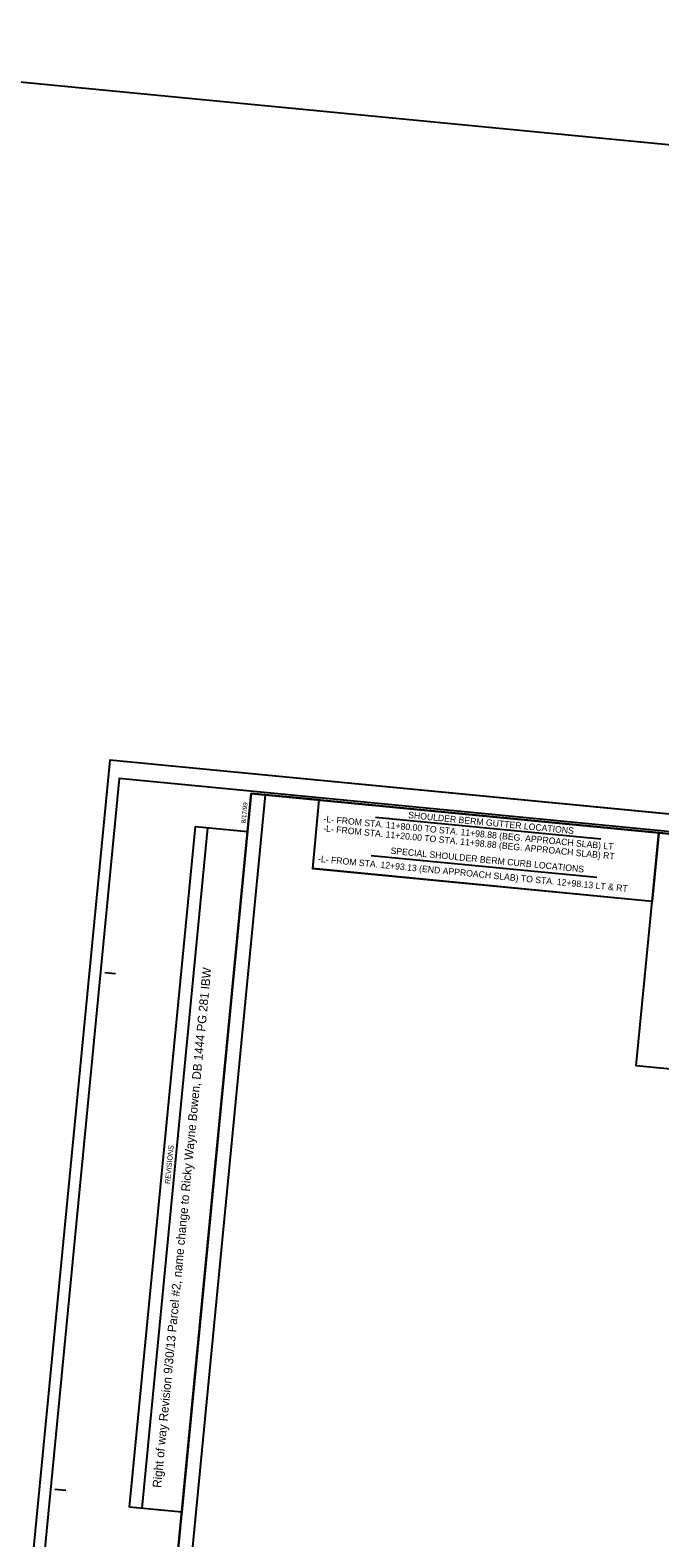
# Model space of a CAD drawing. Extents: x 2060525 to 2062119, y 912110 to 913300.
# Drawn here: x 2060879 to 2061171, y 912603 to 913300 of the extents above; entities that cross this region are included whole.
import ezdxf

# ---------------------------------------------------------------- set-up
doc = ezdxf.new("R2010")
doc.units = 0
for name, color, linetype in [('Prop Conc Shoulder Berm Gutter', 7, 'Continuous'), ('Prop Dimension Text', 7, 'Continuous'), ('Sheet Block Revision CELL', 7, 'Continuous'), ('Sheet Clip Boundary CELL', 7, 'Continuous'), ('Sheet Cutting Line CELL', 7, 'Continuous'), ('Sheet Layout Plan Border', 7, 'Continuous'), ('Sheet Plan CELL', 7, 'Continuous'), ('Sheet Plan Layout CELL', 7, 'Continuous'), ('Sheet Plot Border Inside CELL', 7, 'Continuous'), ('Sheet Plot Border Outside CELL', 7, 'Continuous')]:
    doc.layers.add(name, color=color, linetype=linetype)

msp = doc.modelspace()

# ---------------------------------------------------------------- linework, layer by layer
at = {"layer": 'Prop Conc Shoulder Berm Gutter'}
for p, q in [((2061039.03, 912935.88), (2061143.21, 912925.81)), ((2061037.17, 912918.16), (2061141.35, 912908.09))]:
    msp.add_line(p, q, dxfattribs=at)
at = {"layer": 'Sheet Block Revision CELL'}
msp.add_line((2060931.25, 912616.18), (2060961.67, 912930.97), dxfattribs=at)
msp.add_lwpolyline([(2060925.45, 912616.73), (2060955.88, 912931.52), (2060979.99, 912929.2), (2060949.56, 912614.41)], close=True, dxfattribs=at)
at = {"layer": 'Sheet Clip Boundary CELL'}
msp.add_lwpolyline([(2060947.75, 912528.18), (2061534.24, 912471.49), (2061175.38, 912506.18), (2061182.37, 912578.54), (2061543.72, 912543.62), (2061569, 912805.1), (2061475.51, 912814.14), (2061473.23, 912790.55), (2061159.65, 912820.86), (2061167, 912896.82), (2061010.06, 912911.99), (2061013.14, 912943.82), (2060988.16, 912946.23)], close=True, dxfattribs=at)
at = {"layer": 'Sheet Cutting Line CELL'}
for p, q in [((2060916.27, 912962.22), (2060874.13, 912526.25)), ((2061586.54, 912897.43), (2060916.27, 912962.22))]:
    msp.add_line(p, q, dxfattribs=at)
at = {"layer": 'Sheet Layout Plan Border'}
msp.add_lwpolyline([(2060947.75, 912528.18), (2061530.76, 912471.83), (2061563.03, 912805.68), (2061475.51, 912814.14), (2061483.65, 912898.34), (2060988.16, 912946.23)], close=True, dxfattribs=at)
at = {"layer": 'Sheet Plan CELL'}
for p, q in [((2060981.69, 912946.86), (2060981.69, 912946.86)), ((2060914, 912863.98), (2060918.98, 912863.51)), ((2060890.92, 912625.1), (2060895.9, 912624.61))]:
    msp.add_line(p, q, dxfattribs=at)
for points in [[(2061578.92, 912889.13), (2060981.69, 912946.86), (2060941.28, 912528.81), (2061538.5, 912471.08)], [(2060941.28, 912528.81), (2060981.68, 912946.85), (2061499.26, 912896.83), (2061493.49, 912837.09), (2061573.14, 912829.38), (2061538.5, 912471.08)], [(2061013.14, 912943.82), (2061170.07, 912928.65), (2061167, 912896.82), (2061010.07, 912912.03)], [(2061170.06, 912928.65), (2061483.65, 912898.34), (2061473.22, 912790.47), (2061159.65, 912820.86)]]:
    msp.add_lwpolyline(points, close=True, dxfattribs=at)
at = {"layer": 'Sheet Plan Layout CELL'}
for points in [[(2060625.77, 913299.86), (2060524.78, 912254.76), (2062017.82, 912110.43), (2062098.49, 912945.06), (2061860.35, 912968.08), (2061880.7, 913178.58)], [(2060981.68, 912946.85), (2060941.28, 912528.81), (2061538.5, 912471.08), (2061570.77, 912804.93), (2061475.51, 912814.14), (2061483.65, 912898.34)]]:
    msp.add_lwpolyline(points, close=True, dxfattribs=at)
at = {"layer": 'Sheet Plot Border Inside CELL'}
msp.add_lwpolyline([(2060880.07, 912533.71), (2061543.38, 912469.6), (2061583.98, 912889.64), (2060920.68, 912953.76)], close=True, dxfattribs=at)
at = {"layer": 'Sheet Plot Border Outside CELL'}
msp.add_lwpolyline([(2060874.13, 912526.25), (2061544.4, 912461.46), (2061586.54, 912897.43), (2060916.27, 912962.22)], close=True, dxfattribs=at)

# ---------------------------------------------------------------- texts
at = {"layer": 'Prop Conc Shoulder Berm Gutter'}
for s, p in [('-L- FROM STA. 11+80.00 TO STA. 11+98.88 (BEG. APPROACH SLAB) LT', (2061014.95, 912933.65)), ('SHOULDER BERM GUTTER LOCATIONS', (2061054.1, 912935.44)), ('-L- FROM STA. 11+20.00 TO STA. 11+98.88 (BEG. APPROACH SLAB) RT', (2061014.83, 912929.24)), ('SPECIAL SHOULDER BERM CURB LOCATIONS', (2061045.95, 912918.91)), ('-L- FROM STA. 12+93.13 (END APPROACH SLAB) TO STA. 12+98.13 LT & RT', (2061012.44, 912915.17))]:
    msp.add_text(s, height=3, rotation=354.47872, dxfattribs=at).set_placement(p)
at = {"layer": 'Prop Dimension Text'}
msp.add_text('Right of way Revision 9/30/13 Parcel #2, name change to Ricky Wayne Bowen, DB 1444 PG 281 IBW', height=4, rotation=84.4787, dxfattribs=at).set_placement((2060939.97, 912625.52))
at = {"layer": 'Sheet Block Revision CELL'}
msp.add_text('REVISIONS', height=2.4, rotation=84.4787, dxfattribs=at).set_placement((2060944.11, 912766.1))
at = {"layer": 'Sheet Plan CELL'}
msp.add_text('8/17/99', height=2.1, rotation=84.4787, dxfattribs=at).set_placement((2060979.05, 912932.96))

doc.saveas('drawing.dxf')
